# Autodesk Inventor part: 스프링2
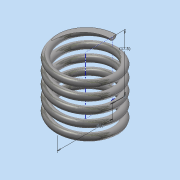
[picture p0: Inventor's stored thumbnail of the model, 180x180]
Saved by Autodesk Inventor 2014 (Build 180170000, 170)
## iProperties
Created: 2016-03
Part Number: 스프링2
Material: 스테인레스 스틸
Document SubType Name: Modeling
Designer: SCD-A13
Density: 8.08 g/cm^3
Appearance: 반연마
Mass: 6.61435 g
Surface Area: 16.696 cm^2
Volume: 0.818608 cm^3
Author: SCD-A13
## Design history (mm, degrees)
sketch "스케치1"
  geometry: L1 (0, 17.5)-(8.5, 17.5); L2 (8.5, 17.5)-(8.5, 0); L3 (8.5, 0)-(0, 0); L4 (0, 0)-(0, 17.5); C1 r 1 at (8.5, 0); 1 further point
  constraints: 8 end point, 2 coincident, 2 parallel, 1 centre point, 1 horizontal, 1 perpendicular
  dimensions: "d0" = 2 diameter of C1; "d1" = 17 diameter of L2 L4; "d2" = 17.5 distance between parallel lines of L1 L3 (derived)
feature "코일1" pitch "d3" = 10; turns "d5" = 5; dims "d4" = 17.5 (= d2), "d6" = 0, angle "d7" = 90 deg, angle "d8" = 90 deg, "d9" = 0, "d10" = 0
node "작업 평면1"
sketch "스케치2"
  geometry: L1 (1, 0)-(-1, 0) reference; 1 further point
  constraints: 1 horizontal alignment
extrude "돌출1" cut sketch "스케치2" stored distance "d12" = 10; taper "d13" = 0 deg
node "작업 평면2"
sketch "스케치3"
  geometry: L1 (9.5, 0)-(7.5, 0) reference; 1 further point
  constraints: 1 horizontal alignment
extrude "돌출2" cut sketch "스케치3" stored distance "d15" = 10; taper "d16" = 0 deg
node "솔리드1"
node "절단 모서리 투영1"
node "절단 모서리 투영2"
other parameters: "d11" = 0, "d14" = 0
